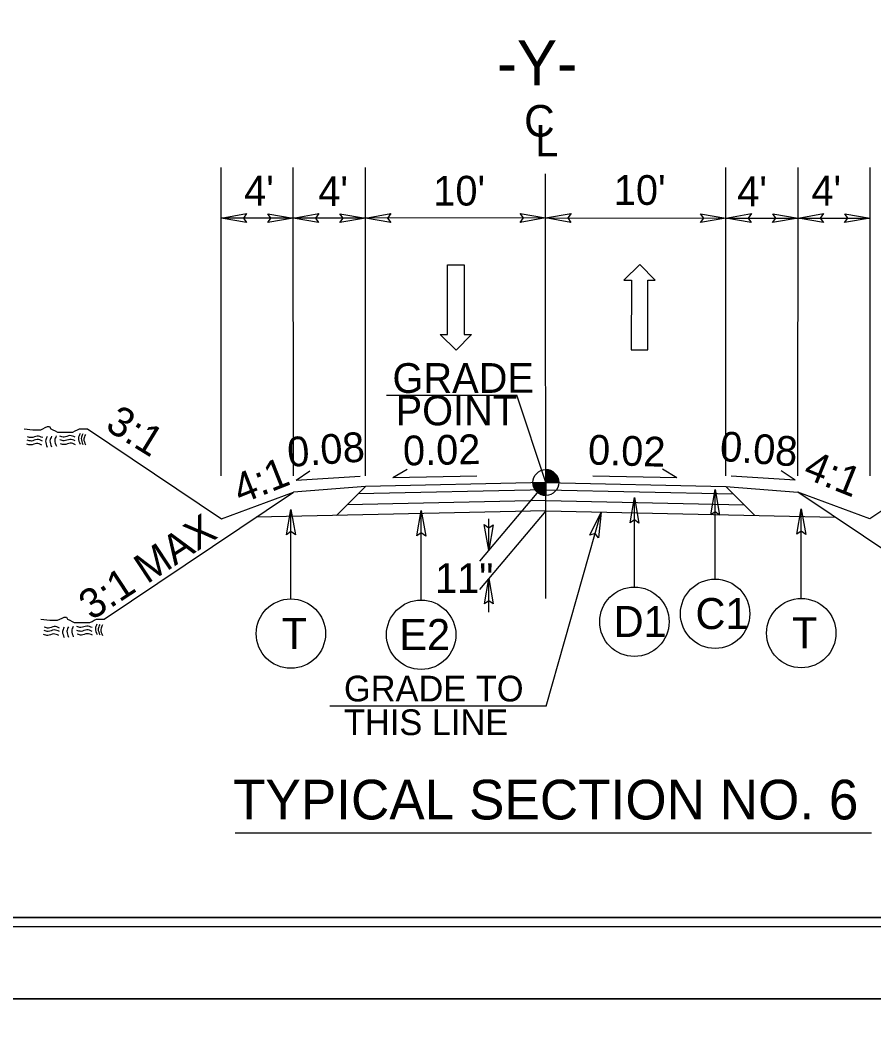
# Model space of a CAD drawing. Extents: x 2241081 to 2251104, y 658534 to 663427.
# Drawn here: x 2248397.6 to 2248634.3, y 660714.3 to 660995.7 of the extents above; entities that cross this region are included whole.
import ezdxf

# ---------------------------------------------------------------- set-up
doc = ezdxf.new("R2010")
doc.units = 0
for name, color, linetype in [('Old_Level_1', 7, 'Continuous'), ('Old_Level_11', 7, 'Continuous'), ('Old_Level_2', 7, 'Continuous'), ('Old_Level_3', 7, 'Continuous'), ('Prop Dimension Text', 7, 'Continuous'), ('Prop Lane Arrow CELL', 7, 'Continuous'), ('Sheet Cutting Line CELL', 7, 'Continuous'), ('Sheet Plan CELL', 7, 'Continuous'), ('Sheet Plot Border Inside CELL', 7, 'Continuous'), ('Sheet Plot Border Outside CELL', 7, 'Continuous'), ('Typical Arrow Superelevation CELL', 7, 'Continuous'), ('Typical Berm Information CELL', 7, 'Continuous'), ('Typical Grade Point Symbol CELL', 7, 'Continuous'), ('Typical Hinge Slope Interstate CELL', 7, 'Continuous'), ('Typical ID Circle CELL', 7, 'Continuous'), ('Typical Terminator CELL', 7, 'Continuous'), ('Typical Text Centerline CELL', 7, 'Continuous'), ('Typical Text Grade Point CELL', 7, 'Continuous'), ('Typical Text ID Circle CELL', 7, 'Continuous'), ('Typical Text Label CELL', 7, 'Continuous')]:
    doc.layers.add(name, color=color, linetype=linetype)

msp = doc.modelspace()

# ---------------------------------------------------------------- linework, layer by layer
at = {"layer": 'Old_Level_1'}
for p, q in [((2248416.23, 660882.39), (2248453.39, 660857.38)), ((2248670.44, 660882.39), (2248633.28, 660857.38)), ((2248420.93, 660829.54), (2248473.38, 660864.84)), ((2248453.39, 660857.38), (2248473.38, 660864.84)), ((2248633.28, 660857.38), (2248613.29, 660864.84)), ((2248665.74, 660829.54), (2248613.29, 660864.84))]:
    msp.add_line(p, q, dxfattribs=at)
for points in [[(2248398.67, 660882.39), (2248401.13, 660882.08), (2248401.75, 660882.08), (2248402.67, 660882.08), (2248403.29, 660882.08), (2248403.91, 660882.39), (2248404.52, 660882.7), (2248405.14, 660883.01), (2248405.75, 660883.01), (2248406.06, 660882.39), (2248406.68, 660882.08), (2248407.3, 660881.77), (2248407.91, 660881.47), (2248408.53, 660881.47), (2248409.14, 660881.47), (2248409.76, 660881.47), (2248410.38, 660881.47), (2248410.99, 660881.47), (2248411.61, 660881.47), (2248412.22, 660881.47), (2248412.84, 660881.77), (2248413.46, 660882.08), (2248414.07, 660882.39), (2248415, 660882.39), (2248415.61, 660882.39), (2248416.23, 660882.39)], [(2248403.36, 660829.54), (2248405.83, 660829.24), (2248406.44, 660829.24), (2248407.37, 660829.24), (2248407.99, 660829.24), (2248408.6, 660829.54), (2248409.22, 660829.85), (2248409.83, 660830.16), (2248410.45, 660830.16), (2248410.76, 660829.54), (2248411.38, 660829.24), (2248411.99, 660828.93), (2248412.61, 660828.62), (2248413.22, 660828.62), (2248413.84, 660828.62), (2248414.46, 660828.62), (2248415.07, 660828.62), (2248415.69, 660828.62), (2248416.31, 660828.62), (2248416.92, 660828.62), (2248417.54, 660828.93), (2248418.15, 660829.24), (2248418.77, 660829.54), (2248419.7, 660829.54), (2248420.31, 660829.54), (2248420.93, 660829.54)]]:
    msp.add_lwpolyline(points, dxfattribs=at)
at = {"layer": 'Old_Level_11'}
msp.add_line((2248543.5, 660805.43), (2248558.71, 660859.27), dxfattribs=at)
at = {"layer": 'Old_Level_2'}
for p, q in [((2248493.38, 660866.41), (2248473.38, 660864.84)), ((2248493.38, 660866.41), (2248485.32, 660858.35)), ((2248543.38, 660865.48), (2248491.33, 660864.36)), ((2248543.38, 660867.48), (2248493.38, 660866.41)), ((2248543.29, 660867.48), (2248593.29, 660866.41)), ((2248543.38, 660865.48), (2248595.34, 660864.36)), ((2248593.29, 660866.41), (2248601.35, 660858.35)), ((2248593.29, 660866.41), (2248613.29, 660864.84)), ((2248543.28, 660862.48), (2248488.27, 660861.3)), ((2248543.39, 660862.48), (2248598.4, 660861.3)), ((2248543.38, 660859.59), (2248463.03, 660857.87)), ((2248543.38, 660859.59), (2248623.64, 660857.88))]:
    msp.add_line(p, q, dxfattribs=at)
for points in [[(2248403.8, 660878.97), (2248402.29, 660879.4), (2248400.71, 660878.99), (2248399.56, 660879.25)], [(2248403.8, 660878.97), (2248402.29, 660879.4), (2248400.71, 660878.99), (2248399.56, 660879.25)], [(2248403.84, 660879.92), (2248402.33, 660880.34), (2248400.75, 660879.94), (2248399.6, 660880.19)], [(2248403.84, 660879.92), (2248402.33, 660880.34), (2248400.75, 660879.94), (2248399.6, 660880.19)], [(2248405.08, 660880.2), (2248404.66, 660878.96), (2248405.12, 660877.31)], [(2248405.08, 660880.2), (2248404.66, 660878.96), (2248405.12, 660877.31)], [(2248406.3, 660880.31), (2248405.87, 660879.07), (2248406.33, 660877.42)], [(2248406.3, 660880.31), (2248405.87, 660879.07), (2248406.33, 660877.42)], [(2248407.61, 660880.41), (2248407.19, 660879.17), (2248407.64, 660877.52)], [(2248407.61, 660880.41), (2248407.19, 660879.17), (2248407.64, 660877.52)], [(2248412.87, 660880.06), (2248411.37, 660880.49), (2248409.77, 660880.08), (2248408.63, 660880.34)], [(2248412.87, 660880.06), (2248411.37, 660880.49), (2248409.77, 660880.08), (2248408.63, 660880.34)], [(2248412.88, 660879.01), (2248411.37, 660879.44), (2248409.79, 660879.03), (2248408.64, 660879.29)], [(2248412.88, 660879.01), (2248411.37, 660879.44), (2248409.79, 660879.03), (2248408.64, 660879.29)], [(2248414.2, 660881.03), (2248413.77, 660879.78), (2248414.23, 660878.14)], [(2248414.2, 660881.03), (2248413.77, 660879.78), (2248414.23, 660878.14)], [(2248414.98, 660880.94), (2248414.56, 660879.7), (2248415.01, 660878.05)], [(2248414.98, 660880.94), (2248414.56, 660879.7), (2248415.01, 660878.05)], [(2248415.71, 660880.8), (2248415.28, 660879.56), (2248415.74, 660877.91)], [(2248415.71, 660880.8), (2248415.28, 660879.56), (2248415.74, 660877.91)], [(2248403.65, 660877.88), (2248402.14, 660878.31), (2248400.55, 660877.9), (2248399.41, 660878.16)], [(2248412.99, 660877.95), (2248411.49, 660878.38), (2248409.89, 660877.98), (2248408.75, 660878.24)], [(2248412.99, 660877.95), (2248411.49, 660878.38), (2248409.89, 660877.98), (2248408.75, 660878.24)], [(2248408.5, 660826.12), (2248406.99, 660826.56), (2248405.41, 660826.15), (2248404.26, 660826.4)], [(2248408.5, 660826.12), (2248406.99, 660826.56), (2248405.41, 660826.15), (2248404.26, 660826.4)], [(2248408.54, 660827.07), (2248407.03, 660827.5), (2248405.45, 660827.09), (2248404.3, 660827.34)], [(2248408.54, 660827.07), (2248407.03, 660827.5), (2248405.45, 660827.09), (2248404.3, 660827.34)], [(2248409.78, 660827.35), (2248409.36, 660826.11), (2248409.82, 660824.47)], [(2248409.78, 660827.35), (2248409.36, 660826.11), (2248409.82, 660824.47)], [(2248410.99, 660827.46), (2248410.57, 660826.22), (2248411.02, 660824.57)], [(2248410.99, 660827.46), (2248410.57, 660826.22), (2248411.02, 660824.57)], [(2248412.31, 660827.56), (2248411.89, 660826.32), (2248412.34, 660824.68)], [(2248412.31, 660827.56), (2248411.89, 660826.32), (2248412.34, 660824.68)], [(2248417.56, 660827.21), (2248416.07, 660827.64), (2248414.47, 660827.24), (2248413.33, 660827.49)], [(2248417.56, 660827.21), (2248416.07, 660827.64), (2248414.47, 660827.24), (2248413.33, 660827.49)], [(2248417.57, 660826.16), (2248416.07, 660826.59), (2248414.48, 660826.18), (2248413.34, 660826.44)], [(2248417.57, 660826.16), (2248416.07, 660826.59), (2248414.48, 660826.18), (2248413.34, 660826.44)], [(2248418.89, 660828.18), (2248418.47, 660826.93), (2248418.92, 660825.29)], [(2248418.89, 660828.18), (2248418.47, 660826.93), (2248418.92, 660825.29)], [(2248419.67, 660828.1), (2248419.25, 660826.85), (2248419.71, 660825.2)], [(2248419.67, 660828.1), (2248419.25, 660826.85), (2248419.71, 660825.2)], [(2248420.4, 660827.95), (2248419.98, 660826.71), (2248420.44, 660825.07)], [(2248420.4, 660827.95), (2248419.98, 660826.71), (2248420.44, 660825.07)], [(2248408.34, 660825.03), (2248406.84, 660825.46), (2248405.25, 660825.06), (2248404.1, 660825.31)], [(2248417.69, 660825.11), (2248416.19, 660825.53), (2248414.59, 660825.13), (2248413.45, 660825.39)], [(2248417.69, 660825.11), (2248416.19, 660825.53), (2248414.59, 660825.13), (2248413.45, 660825.39)]]:
    msp.add_spline(points, degree=3, dxfattribs=at)
at = {"layer": 'Prop Dimension Text'}
for p, q in [((2248453.38, 660869.3), (2248453.33, 660954.89)), ((2248473.38, 660869.31), (2248473.33, 660954.9)), ((2248493.38, 660869.33), (2248493.33, 660954.92)), ((2248593.29, 660869.33), (2248593.34, 660954.92)), ((2248613.29, 660869.31), (2248613.34, 660954.9)), ((2248633.29, 660869.3), (2248633.34, 660954.89)), ((2248473.33, 660940.83), (2248453.33, 660940.82)), ((2248493.33, 660940.85), (2248473.33, 660940.83)), ((2248543.33, 660940.88), (2248493.33, 660940.85)), ((2248543.33, 660940.88), (2248593.33, 660940.85)), ((2248593.33, 660940.85), (2248613.33, 660940.83)), ((2248613.33, 660940.83), (2248633.33, 660940.82)), ((2248543.38, 660867.48), (2248524.98, 660845.67)), ((2248543.38, 660859.59), (2248524.98, 660837.78)), ((2248527.56, 660848.73), (2248527.56, 660857.4)), ((2248527.56, 660831.52), (2248527.56, 660840.84)), ((2248543.5, 660805.43), (2248483.5, 660805.39))]:
    msp.add_line(p, q, dxfattribs=at)
at = {"layer": 'Prop Lane Arrow CELL'}
for p, q in [((2248516.15, 660908.55), (2248516.14, 660927.84)), ((2248516.14, 660927.84), (2248520.69, 660927.84)), ((2248520.69, 660927.84), (2248520.7, 660908.55)), ((2248569.45, 660927.93), (2248565.03, 660923.59)), ((2248573.72, 660923.58), (2248569.45, 660927.93)), ((2248565.03, 660923.59), (2248567.1, 660923.59)), ((2248567.1, 660923.59), (2248567.09, 660904.29)), ((2248571.64, 660904.29), (2248571.65, 660923.59)), ((2248571.65, 660923.59), (2248573.72, 660923.58)), ((2248514.09, 660908.54), (2248516.15, 660908.55)), ((2248518.5, 660904.21), (2248514.09, 660908.54)), ((2248522.77, 660908.55), (2248518.5, 660904.21)), ((2248520.7, 660908.55), (2248522.77, 660908.55)), ((2248567.09, 660904.29), (2248571.64, 660904.29))]:
    msp.add_line(p, q, dxfattribs=at)
at = {"layer": 'Sheet Cutting Line CELL'}
for p, q in [((2247635.51, 660724.27), (2249319.01, 660724.26)), ((2249319.01, 660724.26), (2247635.51, 660724.27))]:
    msp.add_line(p, q, dxfattribs=at)
at = {"layer": 'Sheet Plan CELL'}
for points in [[(2247801.99, 660746.78), (2247801.97, 661796.75), (2249101.96, 661796.79), (2249101.97, 661646.73), (2249302.01, 661646.71), (2249302.01, 660746.78)], [(2249302.03, 661796.78), (2247802, 661796.78), (2247801.99, 660746.78), (2249302.01, 660746.78)]]:
    msp.add_lwpolyline(points, close=True, dxfattribs=at)
at = {"layer": 'Sheet Plot Border Inside CELL'}
msp.add_lwpolyline([(2247648.51, 660744.27), (2249314.49, 660744.28), (2249314.51, 661799.26), (2247648.51, 661799.27)], close=True, dxfattribs=at)
at = {"layer": 'Sheet Plot Border Outside CELL'}
for points in [[(2247635.51, 660724.27), (2249319.01, 660724.26), (2249319.01, 661819.26), (2247635.51, 661819.27)], [(2247635.51, 659629.27), (2249319.01, 659629.26), (2249319.01, 660724.26), (2247635.51, 660724.27)]]:
    msp.add_lwpolyline(points, close=True, dxfattribs=at)
at = {"layer": 'Typical Arrow Superelevation CELL'}
for p, q in [((2248500.99, 660868.82), (2248504.9, 660871.19)), ((2248579.68, 660868.79), (2248575.77, 660871.16)), ((2248474.17, 660868.15), (2248477.98, 660870.68)), ((2248474.17, 660868.15), (2248491.91, 660869.27)), ((2248500.99, 660868.82), (2248524.29, 660869.29)), ((2248579.68, 660868.79), (2248556.38, 660869.26)), ((2248612.5, 660868.15), (2248594.76, 660869.27)), ((2248612.5, 660868.15), (2248608.69, 660870.68))]:
    msp.add_line(p, q, dxfattribs=at)
at = {"layer": 'Typical Grade Point Symbol CELL'}
for p, q in [((2248543.38, 660867.48), (2248535.36, 660891.75)), ((2248543.39, 660871.07), (2248543.38, 660867.48)), ((2248543.38, 660867.48), (2248543.39, 660871.07)), ((2248539.8, 660867.48), (2248543.38, 660867.48)), ((2248543.38, 660867.48), (2248543.38, 660863.9)), ((2248546.96, 660867.48), (2248543.38, 660867.48))]:
    msp.add_line(p, q, dxfattribs=at)
for points in [[(2248543.43, 660867.48), (2248543.43, 660871.07), (2248543.43, 660871.07)], [(2248543.51, 660867.48), (2248543.51, 660871.07)], [(2248543.58, 660867.48), (2248543.58, 660871.06)], [(2248543.65, 660867.48), (2248543.65, 660871.06)], [(2248543.72, 660867.48), (2248543.72, 660871.05)], [(2248543.79, 660867.48), (2248543.79, 660871.04)], [(2248543.86, 660867.48), (2248543.86, 660871.03)], [(2248543.94, 660867.48), (2248543.94, 660871.02)], [(2248544.01, 660867.48), (2248544.01, 660871.01)], [(2248544.08, 660867.48), (2248544.08, 660870.99)], [(2248544.15, 660867.48), (2248544.15, 660870.98)], [(2248544.22, 660867.48), (2248544.22, 660870.96)], [(2248544.29, 660867.48), (2248544.29, 660870.95)], [(2248544.37, 660867.48), (2248544.37, 660870.92)], [(2248544.44, 660867.48), (2248544.44, 660870.91)], [(2248544.22, 660870.09), (2248544.23, 660867.49)], [(2248544.51, 660867.48), (2248544.51, 660870.88)], [(2248544.58, 660867.48), (2248544.58, 660870.86)], [(2248544.65, 660867.48), (2248544.65, 660870.83)], [(2248544.72, 660867.48), (2248544.72, 660870.8)], [(2248544.8, 660867.48), (2248544.8, 660870.77)], [(2248544.87, 660867.48), (2248544.87, 660870.74)], [(2248544.94, 660867.48), (2248544.94, 660870.71)], [(2248544.94, 660869.74), (2248544.94, 660867.49)], [(2248545.01, 660867.48), (2248545.01, 660870.68)], [(2248545.08, 660867.48), (2248545.08, 660870.64)], [(2248545.15, 660867.48), (2248545.15, 660870.6)], [(2248545.23, 660867.48), (2248545.23, 660870.56)], [(2248545.3, 660867.48), (2248545.3, 660870.51)], [(2248545.37, 660867.48), (2248545.37, 660870.46)], [(2248545.44, 660867.48), (2248545.44, 660870.41)], [(2248545.51, 660867.48), (2248545.51, 660870.36)], [(2248545.58, 660867.48), (2248545.58, 660870.31)], [(2248545.66, 660867.48), (2248545.66, 660870.25)], [(2248545.73, 660867.48), (2248545.73, 660870.19)], [(2248545.8, 660867.48), (2248545.8, 660870.13)], [(2248545.87, 660867.48), (2248545.87, 660870.06)], [(2248545.94, 660867.48), (2248545.94, 660869.99)], [(2248546.01, 660867.48), (2248546.01, 660869.91)], [(2248546.08, 660867.48), (2248546.08, 660869.83)], [(2248546.16, 660867.48), (2248546.16, 660869.74)], [(2248546.23, 660867.48), (2248546.23, 660869.66)], [(2248546.3, 660867.48), (2248546.3, 660869.56)], [(2248546.37, 660867.48), (2248546.37, 660869.46)], [(2248546.44, 660867.48), (2248546.44, 660869.35)], [(2248546.51, 660867.48), (2248546.51, 660869.22)], [(2248546.59, 660867.48), (2248546.59, 660869.08)], [(2248546.66, 660867.48), (2248546.66, 660868.93)], [(2248546.73, 660867.48), (2248546.73, 660868.77)], [(2248546.8, 660867.48), (2248546.8, 660868.55)], [(2248546.87, 660867.48), (2248546.87, 660868.3)], [(2248539.84, 660866.98), (2248539.84, 660867.48)], [(2248539.91, 660866.61), (2248539.91, 660867.48)], [(2248539.98, 660866.36), (2248539.98, 660867.48)], [(2248540.05, 660866.16), (2248540.05, 660867.48)], [(2248540.13, 660866), (2248540.13, 660867.48)], [(2248540.2, 660865.85), (2248540.2, 660867.48)], [(2248540.27, 660865.72), (2248540.27, 660867.48)], [(2248540.34, 660865.6), (2248540.34, 660867.48)], [(2248540.41, 660865.49), (2248540.41, 660867.48)], [(2248540.48, 660865.38), (2248540.48, 660867.48)], [(2248540.55, 660865.29), (2248540.55, 660867.48)], [(2248540.63, 660865.2), (2248540.63, 660867.48)], [(2248540.7, 660865.11), (2248540.7, 660867.48)], [(2248540.77, 660865.03), (2248540.77, 660867.48)], [(2248540.84, 660864.96), (2248540.84, 660867.48)], [(2248540.91, 660864.89), (2248540.91, 660867.48)], [(2248540.98, 660864.83), (2248540.98, 660867.48)], [(2248541.06, 660864.76), (2248541.06, 660867.48)], [(2248541.13, 660864.7), (2248541.13, 660867.48)], [(2248541.2, 660867.48), (2248541.2, 660865.82)], [(2248541.2, 660864.64), (2248541.2, 660867.48)], [(2248541.27, 660864.6), (2248541.27, 660867.48)], [(2248541.34, 660864.54), (2248541.34, 660867.48)], [(2248541.41, 660864.49), (2248541.41, 660867.48)], [(2248541.49, 660864.44), (2248541.49, 660867.48)], [(2248541.56, 660864.41), (2248541.56, 660867.48)], [(2248541.63, 660864.37), (2248541.63, 660867.48)], [(2248541.7, 660864.33), (2248541.7, 660867.48)], [(2248541.77, 660864.29), (2248541.77, 660867.48)], [(2248541.84, 660864.25), (2248541.84, 660867.48)], [(2248541.92, 660864.22), (2248541.92, 660867.48)], [(2248541.99, 660864.19), (2248541.99, 660867.48)], [(2248542.06, 660864.16), (2248542.06, 660867.48)], [(2248542.13, 660864.13), (2248542.13, 660867.48)], [(2248542.2, 660864.1), (2248542.2, 660867.48)], [(2248542.27, 660864.08), (2248542.27, 660867.48)], [(2248542.35, 660864.06), (2248542.35, 660867.48)], [(2248542.42, 660864.04), (2248542.42, 660867.48)], [(2248542.49, 660864.02), (2248542.49, 660867.48)], [(2248542.56, 660864), (2248542.56, 660867.48)], [(2248542.63, 660863.98), (2248542.63, 660867.48)], [(2248542.7, 660863.97), (2248542.7, 660867.48)], [(2248542.77, 660863.95), (2248542.77, 660867.48)], [(2248542.84, 660867.48), (2248542.85, 660864.8)], [(2248542.85, 660863.94), (2248542.85, 660867.48)], [(2248542.92, 660863.94), (2248542.92, 660867.48)], [(2248542.99, 660863.93), (2248542.99, 660867.48)], [(2248543.06, 660863.92), (2248543.06, 660867.48)], [(2248543.13, 660863.91), (2248543.13, 660867.48)], [(2248543.2, 660863.91), (2248543.2, 660867.48)], [(2248543.28, 660863.9), (2248543.28, 660867.48)], [(2248543.35, 660863.9), (2248543.35, 660863.9), (2248543.35, 660867.48)], [(2248546.94, 660867.48), (2248546.94, 660867.87)]]:
    msp.add_lwpolyline(points, dxfattribs=at)
msp.add_circle((2248543.38, 660867.48), 3.58, dxfattribs=at)
for start, end in [(359.9905, 89.9905), (179.9905, 269.9905)]:
    msp.add_arc((2248543.38, 660867.48), 3.58, start, end, dxfattribs=at)
at = {"layer": 'Typical ID Circle CELL'}
for p, q in [((2248590.33, 660840.66), (2248590.33, 660865.51)), ((2248567.94, 660838.46), (2248567.94, 660863.31)), ((2248472.67, 660835.16), (2248472.67, 660860.02)), ((2248508.81, 660834.84), (2248508.81, 660859.7)), ((2248614.23, 660835.3), (2248614.23, 660860.16))]:
    msp.add_line(p, q, dxfattribs=at)
for centre in [(2248590.34, 660831.05), (2248567.94, 660828.84), (2248472.67, 660825.55), (2248508.81, 660825.23), (2248614.23, 660825.69)]:
    msp.add_circle(centre, 9.62, dxfattribs=at)
at = {"layer": 'Typical Terminator CELL'}
for points in [[(2248460.37, 660939.62), (2248453.33, 660940.82), (2248460.4, 660942.08), (2248459.51, 660940.83)], [(2248466.3, 660942.04), (2248473.33, 660940.83), (2248466.27, 660939.58), (2248467.16, 660940.83)], [(2248480.37, 660939.63), (2248473.33, 660940.83), (2248480.4, 660942.09), (2248479.51, 660940.84)], [(2248486.3, 660942.05), (2248493.33, 660940.85), (2248486.27, 660939.59), (2248487.16, 660940.84)], [(2248500.37, 660939.64), (2248493.33, 660940.85), (2248500.4, 660942.1), (2248499.51, 660940.85)], [(2248536.3, 660942.08), (2248543.33, 660940.88), (2248536.27, 660939.62), (2248537.16, 660940.87)], [(2248550.36, 660939.66), (2248543.33, 660940.88), (2248550.4, 660942.12), (2248549.51, 660940.87)], [(2248586.31, 660942.06), (2248593.33, 660940.85), (2248586.26, 660939.6), (2248587.16, 660940.85)], [(2248600.36, 660939.63), (2248593.33, 660940.85), (2248600.4, 660942.09), (2248599.51, 660940.84)], [(2248606.31, 660942.05), (2248613.33, 660940.83), (2248606.26, 660939.59), (2248607.16, 660940.84)], [(2248620.36, 660939.62), (2248613.33, 660940.83), (2248620.4, 660942.08), (2248619.51, 660940.83)], [(2248626.31, 660942.04), (2248633.33, 660940.82), (2248626.26, 660939.58), (2248627.16, 660940.83)], [(2248589.12, 660858.48), (2248590.33, 660865.51), (2248591.58, 660858.45), (2248590.33, 660859.34)], [(2248566.73, 660856.28), (2248567.94, 660863.31), (2248569.19, 660856.24), (2248567.94, 660857.14)], [(2248471.46, 660852.99), (2248472.67, 660860.02), (2248473.92, 660852.95), (2248472.67, 660853.85)], [(2248507.6, 660852.67), (2248508.81, 660859.7), (2248510.06, 660852.63), (2248508.81, 660853.53)], [(2248613.02, 660853.13), (2248614.23, 660860.16), (2248615.48, 660853.09), (2248614.23, 660853.98)], [(2248555.63, 660852.83), (2248558.71, 660859.27), (2248557.99, 660852.12), (2248557.03, 660853.33)], [(2248528.77, 660855.76), (2248527.56, 660848.73), (2248526.31, 660855.8), (2248527.56, 660854.9)], [(2248526.35, 660833.81), (2248527.56, 660840.84), (2248528.81, 660833.77), (2248527.56, 660834.67)]]:
    msp.add_lwpolyline(points, close=True, dxfattribs=at)
at = {"layer": 'Typical Text Centerline CELL'}
msp.add_line((2248543.4, 660835.31), (2248543.33, 660953.14), dxfattribs=at)
at = {"layer": 'Typical Text Grade Point CELL'}
msp.add_line((2248499.23, 660891.72), (2248535.36, 660891.75), dxfattribs=at)
at = {"layer": 'Typical Text Label CELL'}
msp.add_line((2248457.21, 660770.3), (2248633.69, 660770.3), dxfattribs=at)

# ---------------------------------------------------------------- texts
at = {"layer": 'Old_Level_3'}
for s, p in [('GRADE TO', (2248487.4, 660806.74)), ('THIS LINE', (2248487.4, 660797.39))]:
    msp.add_text(s, height=7.131, rotation=359.9999, dxfattribs=at).set_placement(p)
at = {"layer": 'Prop Dimension Text'}
for s, height, rotation, p in [('-Y-', 12.5, 0.0349, (2248529.81, 660977.65)), ("4'", 8.25, 0.0349, (2248459.71, 660944.32)), ("10'", 8.25, 0.0349, (2248512.17, 660944.31)), ("10'", 8.25, 359.965, (2248562.23, 660944.51)), ("4'", 8.25, 359.965, (2248617.03, 660944.32)), ("4'", 8.25, 0.0349, (2248480.28, 660944.15)), ("4'", 8.25, 359.965, (2248596.46, 660944.15)), ('11"', 8.25, 359.9999, (2248512.65, 660836.81))]:
    msp.add_text(s, height=height, rotation=rotation, dxfattribs=at).set_placement(p)
at = {"layer": 'Typical Berm Information CELL'}
for s, rotation, p in [('0.08', 4.262, (2248471.98, 660871.76)), ('0.02 ', 1.1459, (2248503.84, 660872.19)), ('0.02 ', 358.1916, (2248554.98, 660872.5)), ('0.08', 355.7379, (2248591.45, 660873.5))]:
    msp.add_text(s, height=8.25, rotation=rotation, dxfattribs=at).set_placement(p)
at = {"layer": 'Typical Hinge Slope Interstate CELL'}
for s, rotation, p in [('3:1', 328.4414, (2248420.86, 660882.35)), ('4:1', 21.6462, (2248458.72, 660861.42)), ('4:1', 337.962, (2248614.39, 660869)), ('3:1 MAX', 33.3696, (2248417.42, 660829.06))]:
    msp.add_text(s, height=8.25, rotation=rotation, dxfattribs=at).set_placement(p)
at = {"layer": 'Typical Text Centerline CELL'}
for s, rotation, p in [('C', 0.0349, (2248537.37, 660963.45)), ('L', 359.9818, (2248540.4, 660957.95))]:
    msp.add_text(s, height=8.76, rotation=rotation, dxfattribs=at).set_placement(p)
at = {"layer": 'Typical Text Grade Point CELL'}
for s, p in [('GRADE', (2248500.85, 660892.34)), ('POINT', (2248501.73, 660883.34))]:
    msp.add_text(s, height=8.25, rotation=0.0349, dxfattribs=at).set_placement(p)
at = {"layer": 'Typical Text ID Circle CELL'}
for s, height, p in [('C1', 8.608, (2248584.89, 660826.81)), ('D1', 8.608, (2248562.19, 660824.61)), ('T', 8.61, (2248470.1, 660821.31)), ('E2', 8.608, (2248502.75, 660820.99)), ('T', 8.61, (2248611.67, 660821.45))]:
    msp.add_text(s, height=height, rotation=359.9999, dxfattribs=at).set_placement(p)
at = {"layer": 'Typical Text Label CELL'}
msp.add_text('TYPICAL SECTION NO. 6', height=11.0106, dxfattribs=at).set_placement((2248456.62, 660773.99))

doc.saveas('drawing.dxf')
